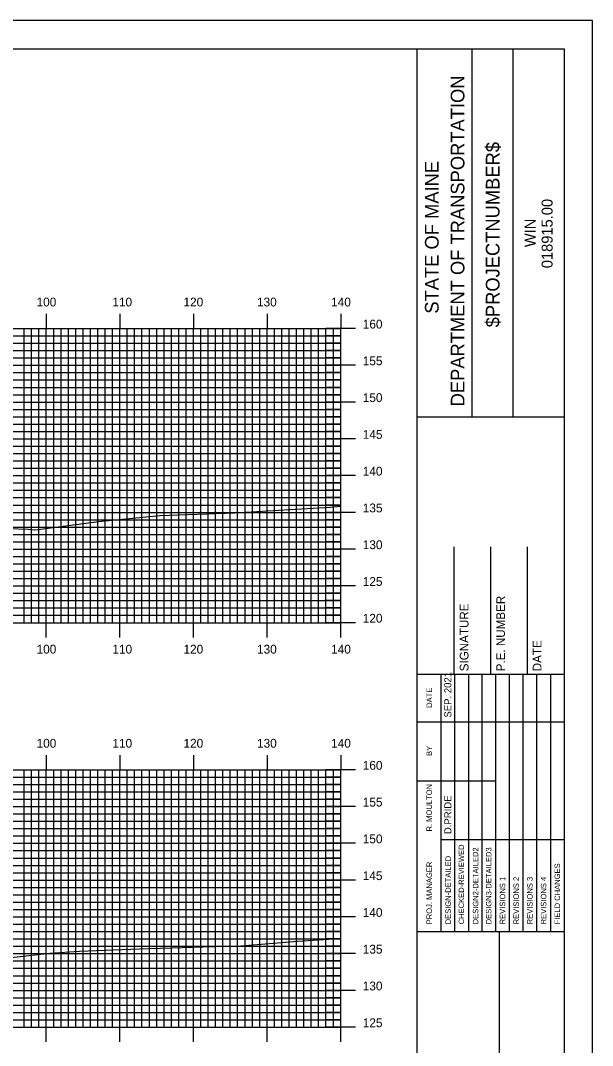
# Model space of a CAD drawing. Extents: x 850966 to 851310, y 364661 to 364881.
# Drawn here: x 851228.7 to 851306.4, y 364741.9 to 364881.3 of the extents above; entities that cross this region are included whole.
import ezdxf

# ---------------------------------------------------------------- set-up
doc = ezdxf.new("R2010")
doc.units = 0
for name, color, linetype in [('BORDER', 7, 'Continuous'), ('H_V ANNOTATION', 7, 'Continuous'), ('MAJOR', 7, 'Continuous'), ('MINOR', 7, 'Continuous'), ('PLOT BOUNDARY', 7, 'Continuous'), ('S_Roadway_Centerline', 7, 'Continuous')]:
    doc.layers.add(name, color=color, linetype=linetype)

msp = doc.modelspace()

# ---------------------------------------------------------------- linework, layer by layer
at = {"layer": 'BORDER'}
for p, q in [((851282.62, 364667.37), (851282.62, 364877.37)), ((851290.07, 364827.36), (851290.07, 364877.36)), ((851295.66, 364827.36), (851295.66, 364877.36)), ((851282.62, 364827.36), (851302.62, 364827.36)), ((851287.62, 364792.38), (851287.62, 364809.67)), ((851292.62, 364792.38), (851292.62, 364809.67)), ((851297.62, 364792.38), (851297.62, 364809.67)), ((851282.62, 364792.38), (851302.62, 364792.38)), ((851282.62, 364757.38), (851302.62, 364757.38)), ((851293.8, 364687.38), (851293.8, 364757.38))]:
    msp.add_line(p, q, dxfattribs=at)
msp.add_lwpolyline([(850982.62, 364667.37), (851302.62, 364667.37), (851302.62, 364877.37), (850982.62, 364877.37)], close=True, dxfattribs=at)
for points in [[(851285.85, 364785.88), (851285.85, 364792.38)], [(851287.71, 364757.38), (851287.71, 364792.38)], [(851289.57, 364792.38), (851289.57, 364757.38)], [(851291.44, 364757.38), (851291.44, 364792.38)], [(851293.3, 364757.38), (851293.3, 364792.38)], [(851295.16, 364757.38), (851295.16, 364792.38)], [(851297.03, 364757.38), (851297.03, 364792.38)], [(851298.89, 364757.38), (851298.89, 364792.38)], [(851300.75, 364757.38), (851300.75, 364792.38)], [(851285.85, 364757.38), (851285.85, 364790.96)], [(851282.62, 364785.88), (851302.62, 364785.88)], [(851282.62, 364777.88), (851285.85, 364777.88)], [(851285.85, 364777.88), (851293.3, 364777.88)], [(851285.85, 364769.88), (851302.62, 364769.88)]]:
    msp.add_lwpolyline(points, dxfattribs=at)
at = {"layer": 'MAJOR'}
for p, q in [((851232.22, 364841.37), (851232.22, 364839.37)), ((851242.22, 364841.37), (851242.22, 364839.37)), ((851252.22, 364841.37), (851252.22, 364839.37)), ((851262.22, 364841.37), (851262.22, 364839.37)), ((851272.22, 364841.37), (851272.22, 364839.37)), ((850992.22, 364839.37), (851272.22, 364839.37)), ((850992.22, 364839.37), (851272.22, 364839.37)), ((851232.22, 364799.37), (851232.22, 364839.37)), ((851242.22, 364799.37), (851242.22, 364839.37)), ((851252.22, 364799.37), (851252.22, 364839.37)), ((851262.22, 364799.37), (851262.22, 364839.37)), ((851274.22, 364839.37), (851270.21, 364839.37)), ((851272.22, 364799.37), (851272.22, 364839.37)), ((851272.22, 364799.37), (851272.22, 364839.37)), ((850992.22, 364834.37), (851272.22, 364834.37)), ((851274.22, 364834.37), (851270.21, 364834.37)), ((850992.22, 364829.37), (851272.22, 364829.37)), ((851274.22, 364829.37), (851270.21, 364829.37)), ((850992.22, 364824.37), (851272.22, 364824.37)), ((851274.22, 364824.37), (851270.21, 364824.37)), ((850992.22, 364819.37), (851272.22, 364819.37)), ((851274.22, 364819.37), (851270.21, 364819.37)), ((850992.22, 364814.37), (851272.22, 364814.37)), ((851274.22, 364814.37), (851270.21, 364814.37)), ((850992.22, 364809.37), (851272.22, 364809.37)), ((851274.22, 364809.37), (851270.21, 364809.37)), ((850992.22, 364804.37), (851272.22, 364804.37)), ((851274.22, 364804.37), (851270.21, 364804.37)), ((850992.22, 364799.37), (851272.22, 364799.37)), ((850992.22, 364799.37), (851272.22, 364799.37)), ((851232.22, 364797.37), (851232.22, 364799.37)), ((851242.22, 364797.37), (851242.22, 364799.37)), ((851252.22, 364797.37), (851252.22, 364799.37)), ((851262.22, 364797.37), (851262.22, 364799.37)), ((851274.22, 364799.37), (851270.21, 364799.37)), ((851272.22, 364797.37), (851272.22, 364799.37)), ((851232.22, 364781.37), (851232.22, 364779.37)), ((851242.22, 364781.37), (851242.22, 364779.37)), ((851252.22, 364781.37), (851252.22, 364779.37)), ((851262.22, 364781.37), (851262.22, 364779.37)), ((851272.22, 364781.37), (851272.22, 364779.37)), ((850992.22, 364779.37), (851272.22, 364779.37)), ((850992.22, 364779.37), (851272.22, 364779.37)), ((851232.22, 364744.37), (851232.22, 364779.37)), ((851242.22, 364744.37), (851242.22, 364779.37)), ((851252.22, 364744.37), (851252.22, 364779.37)), ((851262.22, 364744.37), (851262.22, 364779.37)), ((851274.22, 364779.37), (851270.21, 364779.37)), ((851272.22, 364744.37), (851272.22, 364779.37)), ((851272.22, 364744.37), (851272.22, 364779.37)), ((850992.22, 364774.37), (851272.22, 364774.37)), ((851274.22, 364774.37), (851270.21, 364774.37)), ((850992.22, 364769.37), (851272.22, 364769.37)), ((851274.22, 364769.37), (851270.21, 364769.37)), ((850992.22, 364764.37), (851272.22, 364764.37)), ((851274.22, 364764.37), (851270.21, 364764.37)), ((850992.22, 364759.37), (851272.22, 364759.37)), ((851274.22, 364759.37), (851270.21, 364759.37)), ((850992.22, 364754.37), (851272.22, 364754.37)), ((851274.22, 364754.37), (851270.21, 364754.37)), ((850992.22, 364749.37), (851272.22, 364749.37)), ((851274.22, 364749.37), (851270.21, 364749.37)), ((850992.22, 364744.37), (851272.22, 364744.37)), ((850992.22, 364744.37), (851272.22, 364744.37)), ((851232.22, 364742.37), (851232.22, 364744.37)), ((851242.22, 364742.37), (851242.22, 364744.37)), ((851252.22, 364742.37), (851252.22, 364744.37)), ((851262.22, 364742.37), (851262.22, 364744.37)), ((851274.22, 364744.37), (851270.21, 364744.37)), ((851272.22, 364742.37), (851272.22, 364744.37))]:
    msp.add_line(p, q, dxfattribs=at)
at = {"layer": 'MINOR'}
for p, q in [((851229.22, 364799.37), (851229.22, 364839.37)), ((851230.22, 364799.37), (851230.22, 364839.37)), ((851231.22, 364799.37), (851231.22, 364839.37)), ((851233.22, 364799.37), (851233.22, 364839.37)), ((851234.22, 364799.37), (851234.22, 364839.37)), ((851235.22, 364799.37), (851235.22, 364839.37)), ((851236.22, 364799.37), (851236.22, 364839.37)), ((851237.22, 364799.37), (851237.22, 364839.37)), ((851238.22, 364799.37), (851238.22, 364839.37)), ((851239.22, 364799.37), (851239.22, 364839.37)), ((851240.22, 364799.37), (851240.22, 364839.37)), ((851241.22, 364799.37), (851241.22, 364839.37)), ((851243.22, 364799.37), (851243.22, 364839.37)), ((851244.22, 364799.37), (851244.22, 364839.37)), ((851245.22, 364799.37), (851245.22, 364839.37)), ((851246.22, 364799.37), (851246.22, 364839.37)), ((851247.22, 364799.37), (851247.22, 364839.37)), ((851248.22, 364799.37), (851248.22, 364839.37)), ((851249.22, 364799.37), (851249.22, 364839.37)), ((851250.22, 364799.37), (851250.22, 364839.37)), ((851251.22, 364799.37), (851251.22, 364839.37)), ((851253.22, 364799.37), (851253.22, 364839.37)), ((851254.22, 364799.37), (851254.22, 364839.37)), ((851255.22, 364799.37), (851255.22, 364839.37)), ((851256.22, 364799.37), (851256.22, 364839.37)), ((851257.22, 364799.37), (851257.22, 364839.37)), ((851258.22, 364799.37), (851258.22, 364839.37)), ((851259.22, 364799.37), (851259.22, 364839.37)), ((851260.22, 364799.37), (851260.22, 364839.37)), ((851261.22, 364799.37), (851261.22, 364839.37)), ((851263.22, 364799.37), (851263.22, 364839.37)), ((851264.22, 364799.37), (851264.22, 364839.37)), ((851265.22, 364799.37), (851265.22, 364839.37)), ((851266.22, 364799.37), (851266.22, 364839.37)), ((851267.22, 364799.37), (851267.22, 364839.37)), ((851268.22, 364799.37), (851268.22, 364839.37)), ((851269.22, 364799.37), (851269.22, 364839.37)), ((851270.22, 364799.37), (851270.22, 364839.37)), ((851271.22, 364799.37), (851271.22, 364839.37)), ((850992.22, 364838.37), (851272.22, 364838.37)), ((850992.22, 364837.37), (851272.22, 364837.37)), ((851272.22, 364838.37), (851270.21, 364838.37)), ((851272.22, 364837.37), (851270.21, 364837.37)), ((850992.22, 364836.37), (851272.22, 364836.37)), ((851272.22, 364836.37), (851270.21, 364836.37)), ((850992.22, 364835.37), (851272.22, 364835.37)), ((851272.22, 364835.37), (851270.21, 364835.37)), ((850992.22, 364833.37), (851272.22, 364833.37)), ((851272.22, 364833.37), (851270.21, 364833.37)), ((850992.22, 364832.37), (851272.22, 364832.37)), ((851272.22, 364832.37), (851270.21, 364832.37)), ((850992.22, 364831.37), (851272.22, 364831.37)), ((850992.22, 364830.37), (851272.22, 364830.37)), ((851272.22, 364831.37), (851270.21, 364831.37)), ((851272.22, 364830.37), (851270.21, 364830.37)), ((850992.22, 364828.37), (851272.22, 364828.37)), ((851272.22, 364828.37), (851270.21, 364828.37)), ((850992.22, 364827.37), (851272.22, 364827.37)), ((850992.22, 364826.37), (851272.22, 364826.37)), ((851272.22, 364827.37), (851270.21, 364827.37)), ((851272.22, 364826.37), (851270.21, 364826.37)), ((850992.22, 364825.37), (851272.22, 364825.37)), ((851272.22, 364825.37), (851270.21, 364825.37)), ((850992.22, 364823.37), (851272.22, 364823.37)), ((851272.22, 364823.37), (851270.21, 364823.37)), ((850992.22, 364822.37), (851272.22, 364822.37)), ((851272.22, 364822.37), (851270.21, 364822.37)), ((850992.22, 364821.37), (851272.22, 364821.37)), ((851272.22, 364821.37), (851270.21, 364821.37)), ((850992.22, 364820.37), (851272.22, 364820.37)), ((851272.22, 364820.37), (851270.21, 364820.37)), ((850992.22, 364818.37), (851272.22, 364818.37)), ((851272.22, 364818.37), (851270.21, 364818.37)), ((850992.22, 364817.37), (851272.22, 364817.37)), ((850992.22, 364816.37), (851272.22, 364816.37)), ((851272.22, 364817.37), (851270.21, 364817.37)), ((851272.22, 364816.37), (851270.21, 364816.37)), ((850992.22, 364815.37), (851272.22, 364815.37)), ((851272.22, 364815.37), (851270.21, 364815.37)), ((850992.22, 364813.37), (851272.22, 364813.37)), ((850992.22, 364812.37), (851272.22, 364812.37)), ((851272.22, 364813.37), (851270.21, 364813.37)), ((851272.22, 364812.37), (851270.21, 364812.37)), ((850992.22, 364811.37), (851272.22, 364811.37)), ((851272.22, 364811.37), (851270.21, 364811.37)), ((850992.22, 364810.37), (851272.22, 364810.37)), ((851272.22, 364810.37), (851270.21, 364810.37)), ((850992.22, 364808.37), (851272.22, 364808.37)), ((851272.22, 364808.37), (851270.21, 364808.37)), ((850992.22, 364807.37), (851272.22, 364807.37)), ((851272.22, 364807.37), (851270.21, 364807.37)), ((850992.22, 364806.37), (851272.22, 364806.37)), ((850992.22, 364805.37), (851272.22, 364805.37)), ((851272.22, 364806.37), (851270.21, 364806.37)), ((851272.22, 364805.37), (851270.21, 364805.37)), ((850992.22, 364803.37), (851272.22, 364803.37)), ((850992.22, 364802.37), (851272.22, 364802.37)), ((851272.22, 364803.37), (851270.21, 364803.37)), ((851272.22, 364802.37), (851270.21, 364802.37)), ((850992.22, 364801.37), (851272.22, 364801.37)), ((851272.22, 364801.37), (851270.21, 364801.37)), ((850992.22, 364800.37), (851272.22, 364800.37)), ((851272.22, 364800.37), (851270.21, 364800.37)), ((851229.22, 364744.37), (851229.22, 364779.37)), ((851230.22, 364744.37), (851230.22, 364779.37)), ((851231.22, 364744.37), (851231.22, 364779.37)), ((851233.22, 364744.37), (851233.22, 364779.37)), ((851234.22, 364744.37), (851234.22, 364779.37)), ((851235.22, 364744.37), (851235.22, 364779.37)), ((851236.22, 364744.37), (851236.22, 364779.37)), ((851237.22, 364744.37), (851237.22, 364779.37)), ((851238.22, 364744.37), (851238.22, 364779.37)), ((851239.22, 364744.37), (851239.22, 364779.37)), ((851240.22, 364744.37), (851240.22, 364779.37)), ((851241.22, 364744.37), (851241.22, 364779.37)), ((851243.22, 364744.37), (851243.22, 364779.37)), ((851244.22, 364744.37), (851244.22, 364779.37)), ((851245.22, 364744.37), (851245.22, 364779.37)), ((851246.22, 364744.37), (851246.22, 364779.37)), ((851247.22, 364744.37), (851247.22, 364779.37)), ((851248.22, 364744.37), (851248.22, 364779.37)), ((851249.22, 364744.37), (851249.22, 364779.37)), ((851250.22, 364744.37), (851250.22, 364779.37)), ((851251.22, 364744.37), (851251.22, 364779.37)), ((851253.22, 364744.37), (851253.22, 364779.37)), ((851254.22, 364744.37), (851254.22, 364779.37)), ((851255.22, 364744.37), (851255.22, 364779.37)), ((851256.22, 364744.37), (851256.22, 364779.37)), ((851257.22, 364744.37), (851257.22, 364779.37)), ((851258.22, 364744.37), (851258.22, 364779.37)), ((851259.22, 364744.37), (851259.22, 364779.37)), ((851260.22, 364744.37), (851260.22, 364779.37)), ((851261.22, 364744.37), (851261.22, 364779.37)), ((851263.22, 364744.37), (851263.22, 364779.37)), ((851264.22, 364744.37), (851264.22, 364779.37)), ((851265.22, 364744.37), (851265.22, 364779.37)), ((851266.22, 364744.37), (851266.22, 364779.37)), ((851267.22, 364744.37), (851267.22, 364779.37)), ((851268.22, 364744.37), (851268.22, 364779.37)), ((851269.22, 364744.37), (851269.22, 364779.37)), ((851270.22, 364744.37), (851270.22, 364779.37)), ((851271.22, 364744.37), (851271.22, 364779.37)), ((850992.22, 364778.37), (851272.22, 364778.37)), ((850992.22, 364777.37), (851272.22, 364777.37)), ((851272.22, 364778.37), (851270.21, 364778.37)), ((851272.22, 364777.37), (851270.21, 364777.37)), ((850992.22, 364776.37), (851272.22, 364776.37)), ((851272.22, 364776.37), (851270.21, 364776.37)), ((850992.22, 364775.37), (851272.22, 364775.37)), ((851272.22, 364775.37), (851270.21, 364775.37)), ((850992.22, 364773.37), (851272.22, 364773.37)), ((851272.22, 364773.37), (851270.21, 364773.37)), ((850992.22, 364772.37), (851272.22, 364772.37)), ((851272.22, 364772.37), (851270.21, 364772.37)), ((850992.22, 364771.37), (851272.22, 364771.37)), ((850992.22, 364770.37), (851272.22, 364770.37)), ((851272.22, 364771.37), (851270.21, 364771.37)), ((851272.22, 364770.37), (851270.21, 364770.37)), ((850992.22, 364768.37), (851272.22, 364768.37)), ((851272.22, 364768.37), (851270.21, 364768.37)), ((850992.22, 364767.37), (851272.22, 364767.37)), ((850992.22, 364766.37), (851272.22, 364766.37)), ((851272.22, 364767.37), (851270.21, 364767.37)), ((851272.22, 364766.37), (851270.21, 364766.37)), ((850992.22, 364765.37), (851272.22, 364765.37)), ((851272.22, 364765.37), (851270.21, 364765.37)), ((850992.22, 364763.37), (851272.22, 364763.37)), ((851272.22, 364763.37), (851270.21, 364763.37)), ((850992.22, 364762.37), (851272.22, 364762.37)), ((851272.22, 364762.37), (851270.21, 364762.37)), ((850992.22, 364761.37), (851272.22, 364761.37)), ((851272.22, 364761.37), (851270.21, 364761.37)), ((850992.22, 364760.37), (851272.22, 364760.37)), ((851272.22, 364760.37), (851270.21, 364760.37)), ((850992.22, 364758.37), (851272.22, 364758.37)), ((851272.22, 364758.37), (851270.21, 364758.37)), ((850992.22, 364757.37), (851272.22, 364757.37)), ((850992.22, 364756.37), (851272.22, 364756.37)), ((851272.22, 364757.37), (851270.21, 364757.37)), ((851272.22, 364756.37), (851270.21, 364756.37)), ((850992.22, 364755.37), (851272.22, 364755.37)), ((851272.22, 364755.37), (851270.21, 364755.37)), ((850992.22, 364753.37), (851272.22, 364753.37)), ((850992.22, 364752.37), (851272.22, 364752.37)), ((851272.22, 364753.37), (851270.21, 364753.37)), ((851272.22, 364752.37), (851270.21, 364752.37)), ((850992.22, 364751.37), (851272.22, 364751.37)), ((851272.22, 364751.37), (851270.21, 364751.37)), ((850992.22, 364750.37), (851272.22, 364750.37)), ((851272.22, 364750.37), (851270.21, 364750.37)), ((850992.22, 364748.37), (851272.22, 364748.37)), ((851272.22, 364748.37), (851270.21, 364748.37)), ((850992.22, 364747.37), (851272.22, 364747.37)), ((851272.22, 364747.37), (851270.21, 364747.37)), ((850992.22, 364746.37), (851272.22, 364746.37)), ((850992.22, 364745.37), (851272.22, 364745.37)), ((851272.22, 364746.37), (851270.21, 364746.37)), ((851272.22, 364745.37), (851270.21, 364745.37))]:
    msp.add_line(p, q, dxfattribs=at)
at = {"layer": 'PLOT BOUNDARY'}
msp.add_lwpolyline([(850966.43, 364661.25), (851306.43, 364661.25), (851306.43, 364881.25), (850966.43, 364881.25)], close=True, dxfattribs=at)
at = {"layer": 'S_Roadway_Centerline'}
for points in [[(851175.19, 364813.36), (851180.02, 364811.75), (851180.13, 364811.73), (851181.59, 364811.83), (851197.27, 364812.43), (851207.28, 364812.55), (851218.7, 364812.43), (851229.81, 364812.08), (851230.74, 364812), (851239.29, 364813.12), (851247.66, 364813.95), (851257.85, 364814.29), (851265.31, 364814.74), (851270.85, 364815.07), (851272.22, 364815.2)], [(851174.97, 364755.57), (851182.92, 364754.02), (851189.42, 364753.91), (851200.51, 364753.81), (851215.81, 364753.16), (851216.58, 364753.13), (851216.84, 364753.15), (851218.07, 364753.25), (851227.43, 364753.86), (851232.7, 364754.44), (851236.72, 364754.71), (851244.84, 364755.03), (851255.04, 364755.34), (851258.64, 364755.43), (851266.41, 364756.05), (851270.58, 364756.32), (851272.22, 364756.39)]]:
    msp.add_lwpolyline(points, dxfattribs=at)

# ---------------------------------------------------------------- texts
at = {"layer": 'BORDER'}
for s, height, p in [('DEPARTMENT OF TRANSPORTATION', 1.8635, (851289.03, 364828.78)), ('$PROJECTNUMBER$', 1.8635, (851293.8, 364839.53)), ('STATE OF MAINE', 1.8635, (851285.53, 364841.39)), ('018915.00', 1.491, (851301.01, 364847.57)), ('WIN', 1.491, (851298.69, 364850.43)), ('P.E. NUMBER', 1.1811, (851294.54, 364792.76)), ('SIGNATURE', 1.181, (851289.58, 364792.76)), ('DATE', 1.181, (851299.5, 364792.76)), ('SEP. 2021', 0.969, (851287.26, 364786.47)), ('DATE', 0.743, (851284.62, 364787.79)), ('BY', 0.743, (851284.62, 364781.25)), ('R. MOULTON', 0.745, (851284.62, 364770.98)), ('D.PRIDE', 0.969, (851287.26, 364770.62)), ('CHECKED-REVIEWED', 0.7455, (851288.98, 364758.35)), ('DESIGN2-DETAILED2', 0.7455, (851290.92, 364758.35)), ('DESIGN3-DETAILED3', 0.7455, (851292.7, 364758.35)), ('PROJ. MANAGER', 0.7455, (851284.62, 364758.35)), ('DESIGN-DETAILED', 0.7455, (851287.19, 364758.35)), ('FIELD CHANGES', 0.7455, (851302.02, 364758.35)), ('REVISIONS 1', 0.7455, (851294.57, 364758.35)), ('REVISIONS 2', 0.7455, (851296.43, 364758.35)), ('REVISIONS 3', 0.7455, (851298.29, 364758.35)), ('REVISIONS 4', 0.7455, (851300.16, 364758.35))]:
    msp.add_text(s, height=height, rotation=90, dxfattribs=at).set_placement(p)
at = {"layer": 'H_V ANNOTATION'}
for s, p in [('100', (851230.9, 364842.37)), ('110', (851241.2, 364842.37)), ('120', (851250.86, 364842.37)), ('130', (851260.85, 364842.37)), ('140', (851270.92, 364842.37)), ('160', (851275.22, 364839.37)), ('155', (851275.22, 364834.37)), ('150', (851275.22, 364829.37)), ('145', (851275.22, 364824.37)), ('140', (851275.22, 364819.37)), ('135', (851275.22, 364814.37)), ('130', (851275.22, 364809.37)), ('125', (851275.22, 364804.37)), ('120', (851275.22, 364799.37)), ('100', (851230.9, 364795.17)), ('110', (851241.2, 364795.17)), ('120', (851250.86, 364795.17)), ('130', (851260.85, 364795.17)), ('140', (851270.92, 364795.17)), ('100', (851230.9, 364782.37)), ('110', (851241.2, 364782.37)), ('120', (851250.86, 364782.37)), ('130', (851260.85, 364782.37)), ('140', (851270.92, 364782.37)), ('160', (851275.22, 364779.37)), ('155', (851275.22, 364774.37)), ('150', (851275.22, 364769.37)), ('145', (851275.22, 364764.37)), ('140', (851275.22, 364759.37)), ('135', (851275.22, 364754.37)), ('130', (851275.22, 364749.37)), ('125', (851275.22, 364744.37))]:
    msp.add_text(s, height=1.2, dxfattribs=at).set_placement(p)

doc.saveas('drawing.dxf')
